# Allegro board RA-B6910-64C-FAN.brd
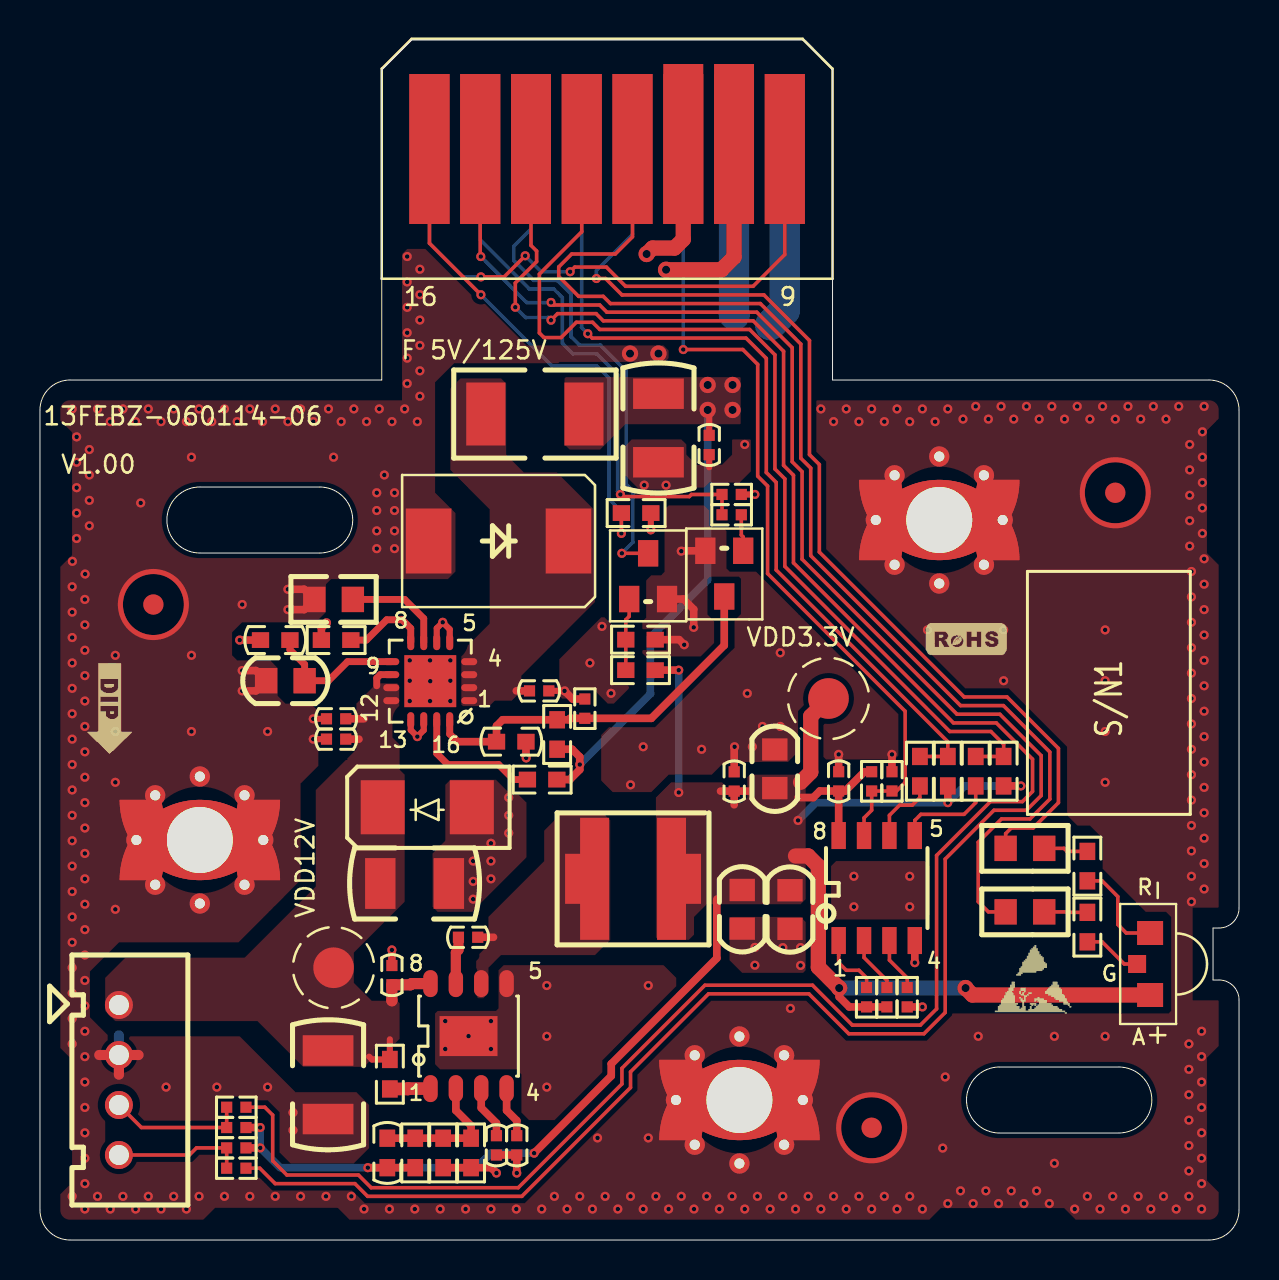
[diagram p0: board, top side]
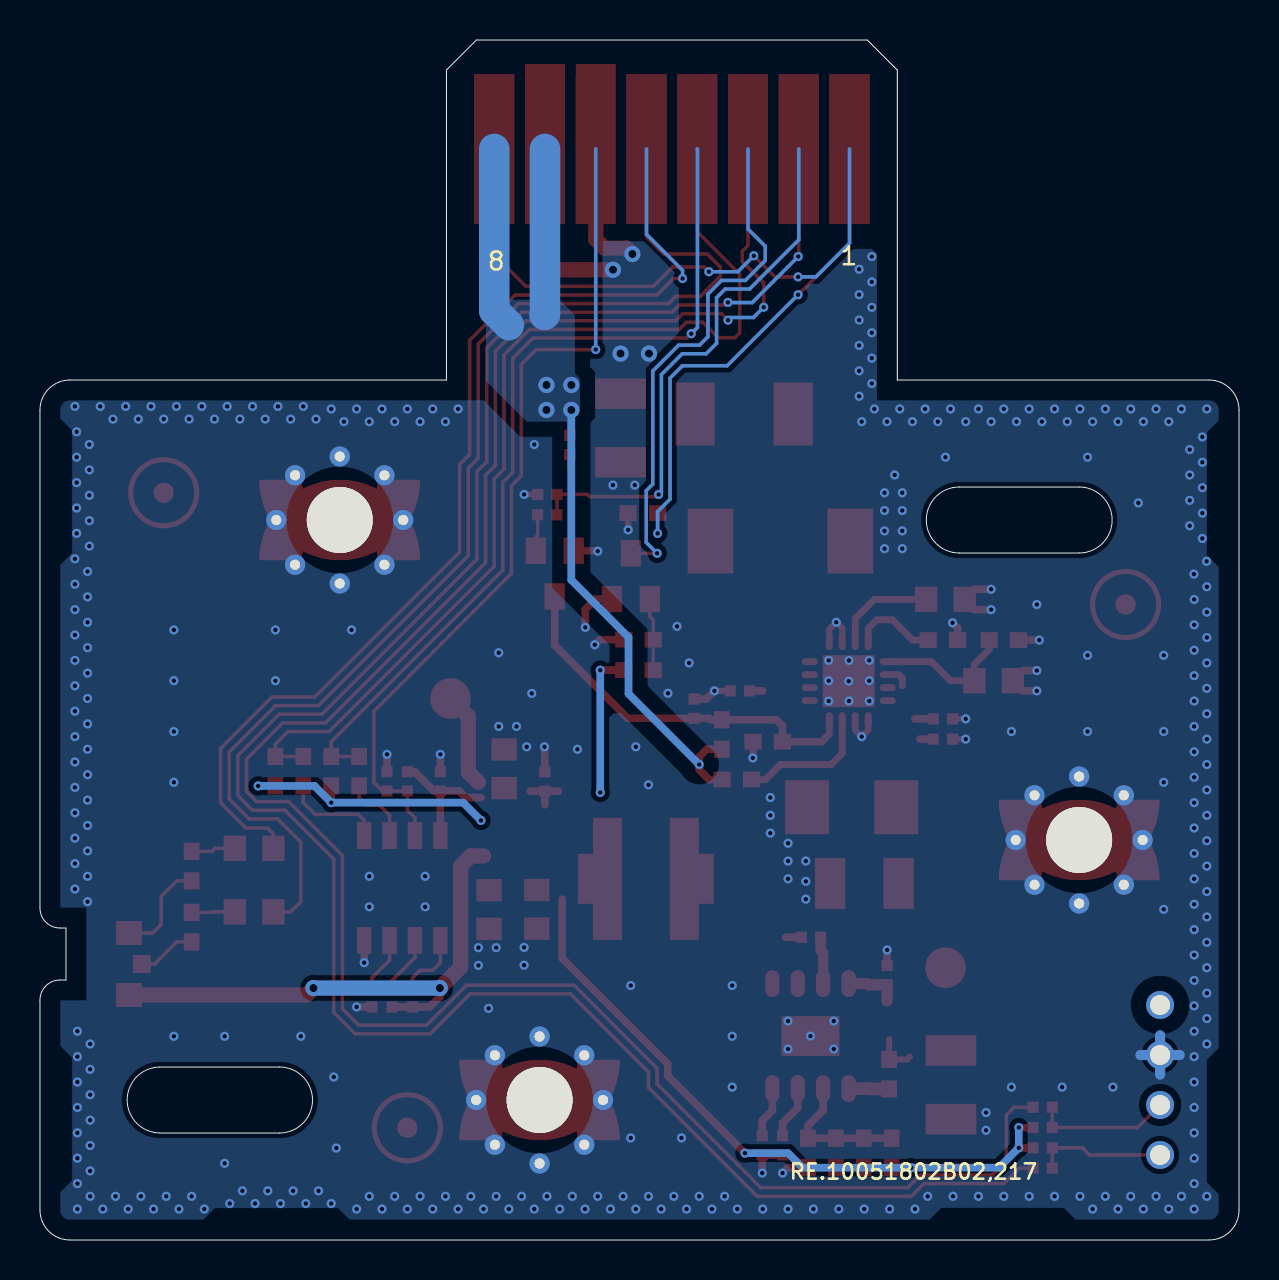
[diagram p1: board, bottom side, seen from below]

Outline 60 x 60 mm; copper layers: TOP, BOTTOM. Coordinates in mm from the lower left corner of the outline.
Outline path: 0,41.5 0,1.5 arc(0.44,0.44) 1.5,0 58.5,0 arc(59.56,0.44) 60,1.5 60,12 arc(59.71,12.71) 59,13 58.7,13 58.7,15.6 59,15.6 arc(59.71,15.89) 60,16.6 60,41.5 arc(59.56,42.56) 58.5,43 39.66,43 39.66,58.5 38.16,60 18.6,60 17.1,58.5 17.1,43 1.5,43 arc(0.44,42.56) 0,41.5 ; 8,37.65 14,37.65 arc(15.65,36) 14,34.35 8,34.35 arc(6.35,36) 8,37.65 ; 48,8.65 54,8.65 arc(55.65,7) 54,5.35 48,5.35 arc(46.35,7) 48,8.65

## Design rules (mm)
nets with their own width: min track width 0.381; nets VDD3.3V

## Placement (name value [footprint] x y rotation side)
C1  X  [C0603]  23.58 24.92 180 top
C2  10uF/25V  [C1210]  18.75 17.83 0 top
C3  10uF/25V  [C1210]  14.42 7.76 270 top
C4  0.1uF/25V  [C0402]  17.61 13.24 90 top
C5  0.1uF/25V  [C0402]  24.98 27.46 0 top
C6  0.1uF/25V  [C0402]  21.42 15.14 0 top
C7  X  [C0603]  17.38 4.35 90 top
C8  1uF/25V  [C0402]  14.82 26.06 180 top
C9  330nF  [C0805]  12.28 27.96 180 top
C10  X  [C0603]  11.77 30 180 top
C11  22uF  [C0805]  37.53 16.52 270 top
C12  X  [C0805]  35.14 16.53 270 top
C13  0.1uF/25V  [C0402]  34.74 22.93 90 top
C14  22uF  [C0805]  36.77 23.56 90 top
C15  1uF/25V  [C0402]  22.84 4.73 270 top
C16  103  [C0402]  23.86 4.73 270 top
C17  0.1uF/25V  [C0402]  39.97 22.93 270 top
C18  10uF/25V  [C1210]  30.95 40.6 270 top
C19  0.1uF/25V  [C0402]  33.49 39.75 270 top
C20  1uF/25V  [C0402]  14.82 25.04 0 top
D1  SMCJ12A  [DO_214AB]  22.95 34.95 180 top
D2  -  [MBRS140T3]  19.38 21.64 0 top
D3  -  [LED_SIDE_2]  55.55 13.8 270 top
F1  5A/125V  [FUSE_0453010]  24.77 41.3 180 top
FD2  -  [MARK]  41.62 5.61 180 top
FD3  -  [MARK]  5.68 31.77 180 top
FD4  -  [MARK]  53.81 37.36 90 top
J1  -  [GF_C210R3_11631_Y]  37.27 54.3 180 top
J3  -  [TJC3_4A]  3.95 11.75 270 top
L1  4.5uH/3A  [NR6045T100M]  29.68 18.06 180 top
L2  100/4A  [L0805]  49.29 16.41 0 top
L3  100/4A  [L0805]  49.29 19.58 0 top
NOREF  -  []  -2 55 0 top
NOREF#2  -  []  49.74 11.96 0 top
NOREF#3  -  []  23.35 7.57 90 top
NOREF#4  -  []  110.22 -1.01 90 top
NOREF#5  -  []  186 -57 180 top
NOREF#6  -  []  -0.99 -7.99 180 top
NOREF#7  -  []  61.01 -39.36 180 top
NOREF#8  -  []  135.78 -0.99 270 top
NOREF#9  -  []  11.78 -0.99 270 top
NOREF#10  -  []  184.99 -39.36 0 top
NOREF#11  -  []  43.78 14.97 90 top
NOREF#12  -  []  -0.99 5.99 180 top
NOREF#13  -  []  172.22 -1.01 90 top
NOREF#14  -  []  46.06 30 0 top
NOREF#15  -  []  60.99 37.36 0 top
NOREF#16  -  []  123.01 -7.99 180 top
NOREF#17  -  []  184.99 37.36 0 top
NOREF#18  -  []  -0.99 37.36 180 top
NOREF#19  -  []  73.78 -0.99 270 top
NOREF#20  -  []  39.33 19.6 0 top
NOREF#21  -  []  4.28 27.2 270 top
NOREF#22  -  []  184.99 5.99 0 top
NOREF#23  -  []  44.41 15.6 90 top
NOREF#24  -  []  20.81 7.57 0 top
NOREF#25  -  []  122.99 5.99 0 top
NOREF#26  -  []  60.99 5.99 0 top
NOREF#27  -  []  18.95 12.19 0 top
NOREF#28  -  []  184.99 -7.99 0 top
NOREF#29  -  []  123.01 -39.36 180 top
NOREF#30  -  []  18.95 8.19 90 top
NOREF#31  -  []  -0.99 -39.36 180 top
NOREF#32  -  []  61.01 -7.99 180 top
NOREF#33  -  []  122.99 37.36 0 top
NOREF#34  -  []  48.22 -1.01 90 top
NOREF#35  -  []  -2 -57 0 bottom
NOREF#36  -  []  186 55 180 bottom
Q1  MMBT3904LT1G  [SOT_23]  30.43 33.19 270 top
Q2  MMBT3904LT1G  [SOT_23]  34.24 33.32 90 top
R1  10K_1%  [R0603]  25.13 23.02 180 top
R2  4.53K_1%  [R0603]  30.05 28.49 180 top
R3  1.91K_1%  [R0603]  30.05 30.02 0 top
R4  10K_1%  [R0603]  17.51 8.29 270 top
R5  10K_1%  [R0603]  18.78 4.35 90 top
R6  47.5K_1%  [R0603]  14.82 30 0 top
R7  200  [R0603]  52.41 15.65 90 top
R8  1K_1%  [R0603]  52.41 18.69 90 top
R9  39K_1%  [R0805]  14.69 32.03 180 top
R10  X  [R0603]  20.18 4.35 270 top
R11  3.01K_1%  [R0603]  21.57 4.35 270 top
R13  4.7K  [R0402]  9.82 4.61 180 top
R16  0  [R0603]  29.83 36.35 0 top
R17  33  [R0402]  9.82 3.59 180 top
R18  4.7K  [R0402]  41.36 12.14 90 top
R19  4.7K  [R0402]  42.38 12.14 90 top
R20  X  [R0402]  42.63 22.93 270 top
R22  0  [R0603]  44.03 23.44 90 top
R24  33  [R0402]  9.82 6.64 0 top
R25  0  [R0603]  46.82 23.44 90 top
R30  4.7K  [R0402]  43.39 12.14 90 top
R31  10K_1%  [R0603]  48.22 23.44 90 top
R33  4.7K  [R0402]  41.62 22.93 270 top
R34  10K_1%  [R0603]  45.43 23.44 90 top
R36  10K_1%  [R0603]  25.88 25.28 90 top
R37  1K  [R0402]  34.61 36.26 0 top
R38  4.7K  [R0402]  27.27 26.57 90 top
R39  4.7K  [R0402]  34.61 37.28 0 top
R40  4.7K  [R0402]  9.82 5.62 180 top
U1  TPS2590RSAR  [QFN_16_EP2M60]  19.53 27.94 180 top
U2  TPS54227  [SOP_8_EP2M90X2M00]  21.45 10.19 0 top
U3  AT24C02C_SSHM_T  [SOP_8]  41.87 17.6 0 top
X1  -  [TEST_80]  39.46 27.08 90 top
X2  -  [SCREW_N_M_3_3MM]  8 20 0 top
X3  -  [SCREW_N_M_3_3MM]  45 36 0 top
X4  -  [SCREW_N_M_3_3MM]  35 7 0 top
X5  -  [TEST_80]  14.69 13.61 270 top

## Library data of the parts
C1-C3 C7 C9-C12 C14 C18 = CAP_NP
C4-C6 C8 C13 C15-C17 C19 C20 = C0402_P: alternate symbols: (c0402;c0402_p)
D1 D2 = DIODE
D3 = LED_SIDE_2
F1 = FUSE
FD2-FD4 = MARK
J1 = GF_C210D7_11631_Y
J3 = TJC3_4A
L1-L3 = Inductor
Q1 Q2 = BCE_NPN
R1-R11 R16 R22 R25 R31 R34 R36 = RESISTOR
R13 R17-R20 R24 R30 R33 R37-R40 = R0402_P: alternate symbols: (r0402;r0402_p)
U1 = TPS2590RSAR
U2 = TPS54227
U3 = 24C02
X1 X5 = TEST_80
X2-X4 = SCREW_N

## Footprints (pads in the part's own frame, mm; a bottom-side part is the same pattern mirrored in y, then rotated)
C0402
  rect 0.559x0.559 smd: 1(-0.483,0) 2(0.483,0)
C0603
  rect 0.864x0.787 smd: 1(-0.737,0) 2(0.737,0)
C0805
  rect 1.118x1.27 smd: 1(-0.965,0) 2(0.965,0)
C1210
  rect 1.524x2.54 smd: 1(-1.714,0) 2(1.714,0)
DO_214AB
  rect 2.286x3.251 smd: 1(3.5,0) 2(-3.5,0)
FUSE_0453010
  rect 1.96x3.15 smd: 1(-2.455,0) 2(2.455,0)
GF_C210R3_11631_Y
  rect 2x7.5 smd: 1(17.78,-0.25) 2(15.24,-0.25) 3(12.7,-0.25) 4(10.16,-0.25) 5(7.62,-0.25) 6(5.08,-0.25) 7(2.54,-0.25) 8(0,-0.25) 9(0,-0.25) 12(7.62,-0.25) 13(10.16,-0.25) 14(12.7,-0.25) 15(15.24,-0.25) 16(17.78,-0.25)
  rect 2x8 smd: 10(2.54,-0.5) 11(5.08,-0.5)
L0805
  rect 1.118x1.27 smd: 1(-0.965,0) 2(0.965,0)
LED_SIDE_2
  rect 1.2x1.3 smd: 1(-1.55,0) 3(1.55,0)
  rect 0.9x0.9 smd: 2(0,-0.65)
MARK
  round 1.016 smd: 1(0,0)
MBRS140T3
  rect 2.2x2.7 smd: 1(2.23,0) 2(-2.23,0)
NR6045T100M
  custom 0.55x0.55 smd: 1(-2.3,0) 2(2.3,0)
QFN_16_EP2M60
  oval 0.8x0.35 smd: 1(-1.95,0.975) 2(-1.95,0.325) 3(-1.95,-0.325) 4(-1.95,-0.975) 9(1.95,-0.975) 10(1.95,-0.325) 11(1.95,0.325) 12(1.95,0.975)
  oval 0.35x0.8 smd: 5(-0.975,-1.95) 6(-0.325,-1.95) 7(0.325,-1.95) 8(0.975,-1.95) 13(0.975,1.95) 14(0.325,1.95) 15(-0.325,1.95) 16(-0.975,1.95)
  rect 2.6x2.6 smd: 17(0,0)
R0402
  rect 0.559x0.559 smd: 1(-0.483,0) 2(0.483,0)
R0603
  rect 0.864x0.787 smd: 1(-0.737,0) 2(0.737,0)
R0805
  rect 1.118x1.27 smd: 1(-0.965,0) 2(0.965,0)
SCREW_N_M_3_3MM
  round 3.3 hole 3.3 unplated: (0,0)
  round 1.016 hole 0.508: 2(-3.175,0) 3(0,3.175) 4(3.175,0) 5(0,-3.175) 6(2.235,2.235) 7(2.235,-2.235) 8(-2.235,-2.235) 9(-2.235,2.235)
  custom 1.003x1.003 smd: 10(0,0) 11(0,0) 12(0,0) 13(0,0)
SOP_8
  rect 0.72x1.35 smd: 1(-1.905,-2.625) 2(-0.635,-2.625) 3(0.635,-2.625) 4(1.905,-2.625) 5(1.905,2.625) 6(0.635,2.625) 7(-0.635,2.625) 8(-1.905,2.625)
SOP_8_EP2M90X2M00
  oval 0.72x1.35 smd: 1(-1.905,-2.625) 2(-0.635,-2.625) 3(0.635,-2.625) 4(1.905,-2.625) 5(1.905,2.625) 6(0.635,2.625) 7(-0.635,2.625) 8(-1.905,2.625)
  rect 2.9x2 smd: 9(0,0)
SOT_23
  rect 1.321x1.016 smd: 1(1.143,-0.947) 2(1.143,0.947) 3(-1.143,0)
TEST_80
  round 2.032 smd: 1(0,0)
TJC3_4A
  round 1.4 hole 1: 1(0,0) 2(2.5,0) 3(5,0) 4(7.5,0)

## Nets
GND: C1.1 C2.2 C3.2 C4.2 C5.2 C8.2 C9.2 C10.2 C11.2 C12.2 C13.2 C14.2 C15.2 C16.2 C17.1 C18.2 C19.2 C20.1 D1.1 D2.1 J1.10(GND_2) J1.11(GND_1) J3.2 Q1.2(E) Q2.2(E) R3.2 R6.1 R9.2 R10.2 R11.2 R16.2 R20.1 R30.1 R38.2 R39.2 U1.5(GND_1) U1.6(R\T\R\Y\) U1.13(GND_2) U1.14(GND_3) U1.17(EPAD) U2.5(GND) U2.9(EPAD) U3.4(GND) X2.2 X2.3 X2.4 X2.5 X2.6 X2.7 X2.8 X2.9 X2.10 X2.11 X2.12 X2.13 X3.2 X3.3 X3.4 X3.5 X3.6 X3.7 X3.8 X3.9 X3.10 X3.11 X3.12 X3.13 X4.2 X4.3 X4.4 X4.5 X4.6 X4.7 X4.8 X4.9 X4.10 X4.11 X4.12 X4.13
VDD3.3V: C7.1 C11.1 C12.1 C13.1 C14.1 C17.2 D3.3(A) L1.1 R2.1 R5.1 R13.1 R18.1 R19.1 R31.1 R33.1 R34.1 R40.1 U3.8(VCC) X1.1
VDD12V: C2.1 C3.1 C4.1 C8.1 C20.2 D2.2 J3.1 R4.1 U1.10(OUT_1) U1.11(OUT_2) U1.12(OUT_3) U2.8(VIN) X5.1
VDD12V_IN: C18.1 C19.1 F1.1 J1.7 J1.8 R1.1 R36.1
FAN_E2_WP: J1.6 R20.2 R33.2 U3.7(WP)
FAN_EN: J1.2 R37.1 R39.1
FAN_LED_GREEN: J1.5 L3.1
FAN_LED_RED: J1.12 L2.1
FAN_POWER_OK#: J1.3 Q1.3(C)
FAN_PWM: J1.15 R17.1
FAN_SCL: J1.4 R22.2 R34.2
FAN_SDA: J1.13 R25.2 R31.2
FAN_TACH: J1.14 R24.2
PRESENT1: J1.1 J1.9
PWM: J3.4 R13.2 R17.2
TACH: J3.3 R24.1 R40.2
TPS2590_EN#: C1.2 Q2.3(C) R36.2 R38.1 U1.16(E\N\)
N356833: C5.1 D1.2 F1.2 U1.1(IN_1) U1.2(IN_2) U1.3(IN_3) U1.4(IN_4)
N16771214: R1.2 U1.15(F\L\T\)
N16771504: R9.1 U1.7(ILIM)
N16771512: R6.2 U1.8(IFLT)
N16772013: C9.1 C10.1 U1.9(CT)
N16778426: C7.2 R5.2 R10.1 R11.1 U2.2(VFB)
N16778448: R4.2 U2.1(EN)
N16778454: C6.1 U2.7(VBST)
N16778460: C15.1 U2.3(VREG5)
N16778464: C16.1 U2.4(SS)
N16778490: C6.2 L1.2 U2.6(SW)
N16779888: Q1.1(B) R2.2 R3.1
N16780436: R18.2 U3.1(A0)
N16780442: R19.2 U3.2(A1)
N16780525: R22.1 U3.6(SCL)
N16780537: R25.1 U3.5(SDA)
N16780545: R30.2 U3.3(A2)
N16791501: Q2.1(B) R37.2
N16806499: J1.16 R16.1
N16830240: D3.2(G) R7.1
N16830247: D3.1(R) R8.1
N16830309: L2.2 R7.2
N16830337: L3.2 R8.2

Pads without a net: FD2 1; FD3 1; FD4 1

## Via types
v1: diameter 0.457, hole 0.229, TOP to BOTTOM, 389 vias
v2: diameter 0.813, hole 0.406, TOP to BOTTOM, 10 vias

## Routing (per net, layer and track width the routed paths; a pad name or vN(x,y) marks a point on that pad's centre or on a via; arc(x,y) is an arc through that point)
GND: length 56.9
  TOP w0.305: R16.2 v1(30.57,35.51) ; C20.1 v1(13.68,25.04) ; U1.13 18.55,25.5 v1(18.88,25.17) 19.2,25.49 U1.14 ; R39.2 v1(35.77,37.28) ; U1.5 20.5,30.53 v1(20.15,30.89) 19.85,30.59 U1.6 ; C5.2 v1(26.25,27.46) ; C19.2 33.49,38.63 ; C8.2 v1(13.68,26.06)
  TOP w0.381: v1(10.12,28.47) 10.81,28.47 C9.2 10.81,27.46 v1(10.12,27.46) ; v1(32.09,34.44) 32.11,34.46 Q2.2 ; C1.1 24.32,24.16 24.33,24.15 v1(24.33,24.1) ; v1(22.84,3.35) 22.57,3.62 R11.2 R10.2 ; Q1.2 32.2,32.05 32.71,31.53 v1(32.71,30.63) ; U3.4 v1(43.78,13.87) ; R38.2 26.66,27.05 v1(26.25,27.46) ; v1(23.86,3.35) C16.2 C15.2 ; R20.1 v1(42.63,24.28) ; R6.1 14.08,30.61 v1(14.34,30.86) ; R30.1 v1(44.16,11.65) ; v1(34.76,24.66) 34.74,24.64 C13.2 ; v1(32.24,29.76) 31.98,30.02 R3.2 ; C10.2 v1(9.99,30) ; v1(12.41,32.54) 13.22,32.54 R9.2 13.22,31.52 v1(12.41,31.52) ; C4.2 v1(17.61,14.5) ; C17.1 v1(39.97,24.28)
  TOP w0.508: 2.97,9.25 J3.2 ; J3.2 4.93,9.25 ; J3.2 3.95,8.27
  TOP w0.762: J1.11 32.19,50.03 31.75,49.6 30.65,49.6 v2(30.36,49.3) ; J1.10 34.73,49.14 34.1,48.51 v2(31.33,48.51)
  BOTTOM w0.508: J3.2 3.95,10.23 ; J3.2 3.95,8.27 ; J3.2 4.93,9.25 ; J3.2 2.97,9.25
  vias: v1(1.61,41.55) v1(1.62,33.93) v1(1.61,32.66) v1(1.61,31.39) v1(1.61,30.12) v1(1.61,28.85) v1(1.61,27.58) v1(1.61,26.31) v1(1.61,25.04) v1(1.61,23.77) v1(1.61,22.5) v1(1.61,21.23) v1(1.61,19.96) v1(1.61,18.69) v1(1.61,17.42) v1(1.61,16.15) v1(1.61,14.88) v1(1.61,13.61) v1(1.61,12.34) v1(1.61,11.07) v1(1.61,9.8) v1(1.61,2.18) v1(1.83,40.16) v1(1.83,38.89) v1(1.83,37.62) v1(1.83,36.35) v1(1.83,35.08) v1(2.26,33.3) v1(2.25,32.03) v1(2.25,30.76) v1(2.25,29.49) v1(2.25,28.22) v1(2.25,26.95) v1(2.25,25.68) v1(2.25,24.41) v1(2.25,23.14) v1(2.25,21.87) v1(2.25,20.6) v1(2.25,19.33) v1(2.25,18.06) v1(2.25,16.79) v1(2.25,15.52) v1(2.25,14.25) v1(2.25,12.98) v1(2.25,11.71) v1(2.25,10.44) v1(2.25,9.17) v1(2.25,7.9) v1(2.25,6.63) v1(2.25,5.36) v1(2.25,4.09) v1(2.25,2.82) v1(2.25,1.55) v1(2.47,39.52) v1(2.47,38.25) v1(2.47,36.98) v1(2.47,35.71) v1(2.88,41.55) v1(2.88,2.18) v1(3.52,40.92) v1(3.52,1.55) v1(3.77,29.23) v1(3.77,25.42) v1(3.77,22.88) v1(3.77,16.53) v1(4.15,41.55) v1(4.15,2.18) v1(4.79,40.92) v1(4.79,1.55) v1(5.04,36.85) v1(5.42,41.55) v1(5.42,2.18) v1(6.06,40.92) v1(6.06,1.55) v1(6.31,7.64) v1(6.69,41.55) v1(6.69,2.18) v1(7.33,40.92) v1(7.33,1.55) v1(7.58,39.14) v1(7.58,29.23) v1(7.58,25.42) v1(7.96,41.55) v1(7.96,2.18) v1(8.6,40.92) v1(8.85,7.64) v1(9.23,41.55) v1(9.23,2.18) v1(9.87,40.92) v1(10.12,31.77) v1(10.5,41.55) v1(10.5,2.18) v1(11.14,40.92) v1(11.39,25.42) v1(11.39,7.64) v1(11.77,41.55) v1(11.77,2.18) v1(12.41,40.92) v1(12.66,6.37) v1(12.66,5.49) v1(13.04,41.55) v1(13.04,2.18) v1(13.68,40.92) v1(14.31,2.18) v1(14.44,41.55) v1(14.69,39.14) v1(15.07,40.92) v1(15.58,2.18) v1(15.71,41.55) v1(16.22,1.55) v1(16.34,40.92) v1(16.85,37.36) v1(16.85,36.47) v1(16.85,35.46) v1(16.85,34.57) v1(16.98,41.55) v1(17.23,38.25) v1(17.49,1.55) v1(17.61,40.92) v1(17.74,37.36) v1(17.74,36.47) v1(17.74,35.46) v1(17.74,34.57) v1(18.25,41.55) v1(18.38,49.17) v1(18.38,47.9) v1(18.38,46.63) v1(18.38,45.36) v1(18.38,44.09) v1(18.38,42.82) v1(18.5,28.98) v1(18.5,27.96) v1(18.5,26.95) v1(18.76,1.55) v1(18.88,40.92) v1(19.01,48.54) v1(19.01,47.27) v1(19.01,46) v1(19.01,44.73) v1(19.01,43.46) v1(19.01,42.19) v1(19.52,28.98) v1(19.53,27.94) v1(19.52,26.95) v1(20.03,1.55) v1(20.28,10.95) v1(20.28,9.55) v1(20.53,28.98) v1(20.53,27.96) v1(20.53,26.95) v1(21.3,1.55) v1(21.45,10.19) v1(21.68,18.95) v1(21.68,17.93) v1(21.68,17.04) v1(22.57,19.84) v1(22.57,18.95) v1(22.57,18.06) v1(22.57,10.95) v1(22.57,9.55) v1(22.57,1.55) v1(23.46,22.12) v1(23.46,21.23) v1(23.46,20.34) v1(23.84,1.55) v1(25.11,1.55) v1(25.36,12.72) v1(25.36,10.18) v1(25.36,7.64) v1(25.74,2.18) v1(26.38,1.55) v1(27.01,2.18) v1(27.52,28.85) v1(27.65,1.55) v1(27.9,5.1) v1(28.12,30.68) v1(28.28,2.18) v1(28.57,27.33) v1(28.92,1.55) v1(29.55,22.76) v1(29.55,2.18) v1(30.19,24.66) v1(30.19,1.55) v1(30.24,37.74) v1(30.44,12.72) v1(30.44,5.1) v1(30.82,2.18) v1(31.33,37.74) v1(31.46,1.55) v1(32.09,2.18) v1(32.73,1.55) v1(33.11,24.54) v1(33.36,2.18) v1(34,1.55) v1(34.63,2.18) v1(35.27,39.78) v1(35.27,1.55) v1(35.39,27.33) v1(35.65,24.66) v1(35.77,14.63) v1(35.77,13.74) v1(35.9,2.18) v1(36.16,25.68) v1(36.54,1.55) v1(37.04,29.36) v1(37.04,25.68) v1(37.17,14.62) v1(37.17,2.18) v1(37.55,11.58) v1(37.81,1.55) v1(38.06,14.62) v1(38.06,13.73) v1(38.44,2.18) v1(39.08,41.55) v1(39.08,1.55) v1(39.71,40.92) v1(39.71,2.18) v1(40.35,41.55) v1(40.35,1.55) v1(40.73,18.19) v1(40.73,16.66) v1(40.98,40.92) v1(40.98,2.18) v1(41.62,41.55) v1(41.62,1.55) v1(42.25,40.92) v1(42.25,2.18) v1(42.89,41.55) v1(42.89,1.55) v1(43.52,40.92) v1(43.52,18.19) v1(43.52,16.66) v1(43.52,2.18) v1(44.16,41.55) v1(44.16,1.55) v1(44.41,30.5) v1(44.79,40.92) v1(45.17,4.6) v1(45.3,8.15) v1(45.43,41.55) v1(45.43,1.82) v1(46.06,2.46) v1(46.19,41.05) v1(46.7,1.82) v1(46.82,41.68) v1(46.95,10.18) v1(47.33,2.46) v1(47.46,41.05) v1(47.97,1.82) v1(48.09,41.68) v1(48.22,30.5) v1(48.22,27.96) v1(48.6,2.46) v1(48.73,41.05) v1(49.24,1.82) v1(49.36,41.68) v1(49.87,2.46) v1(50,41.05) v1(50.51,1.82) v1(50.63,41.68) v1(50.76,10.18) v1(50.76,3.83) v1(51.27,41.05) v1(51.78,1.55) v1(51.9,41.68) v1(52.41,2.18) v1(52.54,41.05) v1(53.05,1.55) v1(53.17,41.68) v1(53.3,30.5) v1(53.3,27.96) v1(53.3,25.42) v1(53.3,22.88) v1(53.3,10.18) v1(53.68,2.18) v1(53.81,41.05) v1(54.32,1.55) v1(54.44,41.68) v1(54.95,2.18) v1(55.08,41.05) v1(55.59,1.55) v1(55.71,41.68) v1(56.22,2.18) v1(56.35,41.05) v1(56.86,1.55) v1(56.98,41.68) v1(57.49,9.8) v1(57.49,8.53) v1(57.49,7.26) v1(57.49,5.99) v1(57.49,4.72) v1(57.49,3.45) v1(57.49,2.18) v1(57.53,39.78) v1(57.53,38.51) v1(57.53,37.24) v1(57.53,35.97) v1(57.53,34.7) v1(57.62,33.43) v1(57.62,32.16) v1(57.62,30.89) v1(57.62,29.62) v1(57.62,28.35) v1(57.62,27.08) v1(57.62,25.81) v1(57.62,24.54) v1(57.62,23.27) v1(57.62,22) v1(57.62,20.73) v1(57.62,19.46) v1(57.62,18.19) v1(57.62,16.92) v1(58.17,40.41) v1(58.17,39.14) v1(58.17,37.87) v1(58.17,36.6) v1(58.17,35.33) v1(58.13,10.44) v1(58.13,9.17) v1(58.13,7.9) v1(58.13,6.63) v1(58.13,5.36) v1(58.13,4.09) v1(58.13,2.82) v1(58.13,1.55) v1(58.25,41.68) v1(58.25,34.06) v1(58.25,32.79) v1(58.25,31.52) v1(58.25,30.25) v1(58.25,28.98) v1(58.25,27.71) v1(58.25,26.44) v1(58.25,25.17) v1(58.25,23.9) v1(58.25,22.63) v1(58.25,21.36) v1(58.25,20.09) v1(58.25,18.82) v1(58.25,17.55) v2(29.53,44.32) v2(30.95,44.32)
VDD3.3V: length 96.5
  TOP w0.381: 37.93,22.12 38.7,22.12 39.02,22.45 C17.2 ; v2(39.99,12.6) 39.99,12.16 40.5,11.65 R18.1 R19.1 ; 33.87,17.04 33.87,14.09 28.59,8.81 28.59,8.2 v1(24.73,4.34) ; R40.1 v1(11.02,5.62) ; R5.1 C7.1 v1(16.4,3.62) ; R33.1 41.26,23.41 40.29,22.45 C17.2 ; C17.2 U3.8 ; 34.74,21.76 C13.1 ; C13.1 35.46,22.44 ; C13.1 34.06,22.44 ; R2.1 v1(31.96,28.49) ; R13.1 v1(11.02,4.61) ; R34.1 v1(45.43,21.87) ; R31.1 v1(49.08,22.7)
  TOP w0.762: v2(39.99,12.6) 38.95,13.64 38.95,18.69 38.44,19.2 37.81,19.2 ; 38.06,22.88 38.57,23.39 38.57,26.19 X1.1 ; v2(46.32,12.6) 46.66,12.25 D3.3
  BOTTOM w0.381: v1(11.02,5.62) 11.02,4.61 v1(11.02,4.61) 12.01,3.62 v1(16.4,3.62) 21.84,3.62 22.57,4.34 v1(24.73,4.34) ; v1(31.96,28.49) v1(31.96,22.38) ; v1(49.08,22.7) 46.26,22.7 v1(45.43,21.87) 38.82,21.87 v1(37.93,20.98)
  BOTTOM w0.762: v2(46.32,12.6) v2(39.99,12.6)
VDD12V: length 7.6
  TOP w0.305: 17.51,10.04 R4.1 16.61,9.03 16.47,9.17
  TOP w0.343: U1.10 17.03,28.27 16.85,28.09 16.85,27.71
  TOP w0.381: C20.2 15.96,25.04 ; C8.1 16.22,26.06
  TOP w0.559: 17.61,11.96 17.61,11.97 C4.1 18.54,12.76 18.6,12.82 U2.8
VDD12V_IN: length 42.4
  TOP w0.305: C19.1 33.49,41.43 v2(33.41,41.5)
  TOP w0.381: R1.1 26.51,23.02 27.01,23.52 v1(27.01,23.77) 27.01,24.15 26.63,24.54 R36.1
  BOTTOM w0.381: v1(27.01,23.77) 30.55,27.31 30.55,30.14 33.41,33 v2(33.41,41.5)
  BOTTOM w1.524: J1.7 34.73,46.28 34.76,46.25 ; J1.8 37.27,46.48 36.54,45.74
  vias: v2(33.41,42.75) v2(34.66,42.75) v2(34.66,41.5)
FAN_E2_WP: length 42.3
  TOP w0.178: v1(32.19,44.52) 35.17,44.52 35.91,43.78 35.91,38.19 36.41,37.7 36.41,33.32 43.29,26.44 43.29,22.88 42.86,22.45 R20.2 R33.2 41.62,21.49 41.24,21.11 U3.7
  BOTTOM w0.178: v1(32.19,44.52) J1.6
FAN_EN: length 27.8
  TOP w0.178: R37.1 R39.1 32.6,37.28 32.49,37.17 29.15,37.17 v1(29.04,37.28)
  BOTTOM w0.178: v1(29.04,37.28) 28.9,37.42 28.9,43.27 27.86,44.31 26.67,44.31 26.14,44.83 26.14,47.12 25.71,47.55 24.49,47.55 22.03,50.01 J1.2
FAN_LED_GREEN: length 52.7
  TOP w0.178: v1(27.84,48.07) 28.3,48.07 29.12,47.25 36.23,47.25 38.5,44.98 38.5,39.27 39,38.77 39,34.4 46.25,27.15 48.39,27.15 50.96,24.58 50.96,21.87 49.7,20.6 48.6,20.6 48.32,20.32 L3.1
  BOTTOM w0.178: v1(27.84,48.07) 27.84,48.48 29.65,50.29 J1.5
FAN_LED_RED: length 60.9
  TOP w0.178: J1.12 29.65,50.16 28.79,49.3 26.61,49.3 25.96,48.65 25.96,48.18 26.95,47.18 28.19,47.18 28.55,46.82 36.05,46.82 38.07,44.8 38.07,39.09 38.57,38.59 38.57,34.22 46.07,26.72 48.21,26.72 50.53,24.4 50.53,22.04 49.54,21.06 48.12,21.06 46.95,19.89 46.95,16.92 47.46,16.41 L2.1
FAN_POWER_OK#: length 25.9
  TOP w0.178: v1(29.12,34.33) Q1.3
  BOTTOM w0.178: J1.3 24.57,50.55 23.71,49.69 23.71,48.98 24.7,47.98 25.89,47.98 26.57,47.3 26.57,45.16 27,44.74 28.04,44.74 29.34,43.45 29.34,37.79 29.67,37.46 29.67,34.88 v1(29.12,34.33)
FAN_PWM: length 107
  TOP w0.178: v1(25.57,46.88) 25.7,46.75 28.01,46.75 28.37,46.39 35.87,46.39 37.64,44.62 37.64,38.91 38.14,38.42 38.14,34.04 45.89,26.29 48.03,26.29 50.1,24.22 50.1,22.22 49.36,21.49 47.74,21.49 45.3,19.05 45.3,11.38 44.23,10.31 40.47,10.31 38.48,12.31 33.45,12.31 29.55,8.41 29.55,7.62 24.11,2.18 16.39,2.18 15.76,2.82 11.77,2.82 11,3.59 R17.1 ; v1(22.06,49.17) 22.03,49.2 J1.15
  BOTTOM w0.178: v1(25.57,46.88) 25.56,46.87 24.36,46.87 v1(22.06,49.17)
FAN_SCL: length 43.9
  TOP w0.178: v1(27.41,45.31) 27.63,45.09 35.33,45.09 36.35,44.08 36.35,38.37 36.84,37.88 36.84,33.5 45.43,24.92 R34.2 R22.2
  BOTTOM w0.178: J1.4 27.1,54.54 27.1,45.63 v1(27.41,45.31)
FAN_SDA: length 50.4
  TOP w0.178: R25.2 R31.2 48.22,24.79 47.59,25.42 45.53,25.42 37.27,33.68 37.27,38.06 36.78,38.55 36.78,44.26 35.51,45.53 28.01,45.53 27.65,45.89 26.84,45.89 26.07,45.12 25.22,45.12 24.99,45.35 24.99,48.3 27.11,50.41 J1.13
FAN_TACH: length 108.7
  TOP w0.178: v1(25.57,45.99) 25.9,46.32 27.83,46.32 28.19,45.96 35.69,45.96 37.21,44.44 37.21,38.73 37.7,38.24 37.7,33.86 45.71,25.86 47.85,25.86 49.67,24.04 49.67,22.43 49.16,21.92 47.56,21.92 44.87,19.23 44.87,11.56 44.05,10.74 40.65,10.74 38.66,12.74 33.27,12.74 29.12,8.59 29.12,7.8 23.93,2.61 16.57,2.61 15.94,3.25 12.36,3.25 11.64,3.96 11.64,6.25 11.25,6.64 R24.2 ; J1.14 24.57,49.73 24.85,49.45 24.85,48.92 23.79,47.85 v1(23.79,46.64)
  BOTTOM w0.178: v1(25.57,45.99) 25.44,46.13 24.3,46.13 v1(23.79,46.64)
PRESENT1: length 30.4
  TOP w0.178: J1.9 37.27,49.27 35.68,47.69 29.3,47.69 28.34,48.65 26.76,48.65 v1(26.53,48.41) ; v1(24.28,49.21) 23.23,48.16 v1(22.06,48.16)
  BOTTOM w0.178: v1(24.28,49.21) 25.08,48.41 26.53,48.41 v1(26.53,48.41) ; J1.1 19.49,49.84 21.17,48.16 v1(22.06,48.16)
PWM: length 6.6
  TOP w0.178: R17.2 R13.2 7.83,4.61 7.48,4.25 J3.4
TACH: length 6.9
  TOP w0.178: R24.1 R40.2 5.08,5.62 J3.3
TPS2590_EN#: length 19.5
  TOP w0.343: U1.16 20.5,25.3 20.71,25.09
  TOP w0.381: 20.71,25.09 20.88,24.92 C1.2 22.85,25.7 23.15,26.01 R36.2 26.46,26.01 26.53,26.08 R38.1 30.59,26.08 34.24,29.73 Q2.3
N356833: length 0.7
  TOP w0.381: C5.1 23.84,27.46
N16771214: length 6.7
  TOP w0.343: U1.15 19.85,24.33 20.41,23.77 22.95,23.77 23.7,23.02 R1.2
N16771504: length 5.1
  TOP w0.343: R9.1 18.25,32.03 19.2,31.07 U1.7
N16771512: length 4.3
  TOP w0.343: U1.8 18.55,30.58 18.12,31.01 17.35,31.01 16.33,30 R6.2
N16772013: length 7.1
  TOP w0.343: C10.1 12.51,29.51 13.24,28.78 C9.1 14.44,27.96 15.39,28.92 U1.9
N16778426: length 7
  TOP w0.381: U2.2 20.81,6.48 21.57,5.72 R11.1 R10.1 R5.2 C7.2
N16778448: length 2
  TOP w0.635: U2.1 18.43,7.57 18.41,7.55 R4.2
N16778454: length 2.4
  TOP w0.508: U2.7 20.81,14.37 20.94,14.5 C6.1
N16778460: length 2.7
  TOP w0.381: U2.3 22.08,6.61 22.84,5.84 C15.1
N16778464: length 2.6
  TOP w0.381: U2.4 23.35,6.48 23.86,5.97 C16.1
N16778490: length 0.8
  TOP w0.381: C6.2 22.69,15.14
N16779888: length 3.6
  TOP w0.178: Q1.1 29.48,31.18 29.31,31.01 R3.1 R2.2
N16780436: length 3.3
  TOP w0.178: U3.1 39.97,14.25 39.97,14.25 39.97,13.87 40.35,13.49 40.98,13.49 41.36,13.1 R18.2
N16780442: length 2.8
  TOP w0.178: R19.2 42.38,12.98 41.24,14.12 U3.2
N16780525: length 3.5
  TOP w0.178: R22.1 44.03,22.7 44.03,22.12 43.65,21.74 43.01,21.74 42.51,21.23 U3.6
N16780537: length 5
  TOP w0.178: U3.5 43.78,20.98 44.08,21.28 46.24,21.28 46.82,21.87 R25.1
N16780545: length 2.7
  TOP w0.178: R30.2 43.39,13.1 42.51,13.99 U3.3
N16791501: length 1.8
  TOP w0.178: R37.2 35.09,35.25 35.19,35.15 Q2.1
N16806499: length 25.5
  TOP w0.178: R16.1 v1(29.09,35.33) ; J1.16 19.49,49.84 21.17,48.16 21.17,48.16 v1(22.06,47.26)
  BOTTOM w0.178: v1(29.09,35.33) 29.09,36.42 28.47,37.04 28.47,43.09 27.85,43.71 25.61,43.71 v1(22.06,47.26)
N16830240: length 2.9
  TOP w0.178: D3.2 54.26,13.8 53.15,14.91 R7.1
N16830247: length 5
  TOP w0.178: R8.1 53.15,17.96 53.94,17.17 53.94,15.77 54.36,15.35 D3.1
N16830309: length 2.2
  TOP w0.178: L2.2 51.37,16.41 51.4,16.38 R7.2
N16830337: length 2.2
  TOP w0.178: L3.2 51.24,19.58 51.4,19.43 R8.2

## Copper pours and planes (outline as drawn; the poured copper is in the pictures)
GND on TOP (solid shape): outline of 184 points within 3.9,30 7.45,33.55
GND on TOP (solid shape): outline of 184 points within 39.84,3.83 43.39,7.39
GND on TOP (solid shape): outline of 184 points within 52.03,35.58 55.59,39.14
GND on TOP: 24.47,5.99 24.09,6.37 24.09,8.28 23.84,8.53 20.03,8.53 19.77,8.79 19.77,11.33 19.9,11.45 22.82,11.45 22.95,11.58 22.95,13.49 23.2,13.74 31.2,13.74 31.84,13.11 31.84,11.96 25.87,5.99
GND on TOP: 1.5,1.02 1.16,1.16 1.02,1.5 1.02,41.5 1.16,41.84 1.5,41.98 18.12,41.98 18.12,49.3 18.38,49.55 19.77,49.55 22.06,47.27 22.06,47.01 24.34,44.73 31.2,44.73 31.46,44.47 31.46,44.09 31.2,43.84 29.93,43.84 30.31,43.46 32.22,43.46 32.66,43.9 32.85,43.71 35.39,43.71 35.39,44.09 35.14,44.35 33.11,44.35 32.47,44.98 30.31,44.98 30.19,44.86 30.19,45.87 29.81,46.25 34,46.25 34.76,47.01 36.03,45.74 36.16,45.87 36.16,46.38 37.93,44.6 37.93,41.43 38.06,41.3 38.74,41.98 58.5,41.98 58.84,41.84 58.98,41.5 58.98,16.62 57.68,16.62 57.68,11.98 58.98,11.98 58.98,1.5 58.84,1.16 58.5,1.02 ; 21 cut-outs
GND on TOP: 20.53,23.01 22.82,23.01 23.58,22.25 23.96,22.25 24.34,21.87 24.34,19.07 21.68,16.41 19.9,16.41 19.65,16.66 19.65,19.33 20.28,19.96 20.28,22.76
GND on TOP: 34.63,16.15 38.06,16.15 38.31,15.9 38.31,13.49 38.19,13.36 35.14,13.36 34.5,13.99 34.5,16.03
GND on BOTTOM: 1.5,1.02 1.16,1.16 1.02,1.5 1.02,41.5 1.16,41.84 1.5,41.98 18.12,41.98 18.12,49.3 18.12,49.3 18.38,49.55 19.78,49.55 24.85,44.49 27.28,44.49 27.9,43.86 28.89,43.86 29.21,44.18 28.03,45.36 28.03,48.31 29.65,49.94 32.07,49.94 32.07,46.38 32.38,46.07 33.44,47.12 33.44,49.94 38.64,49.94 38.64,45.95 38.09,45.39 38.09,42.92 37.43,42.26 37.43,42.14 37.58,41.98 58.5,41.98 58.84,41.84 58.98,41.5 58.98,16.62 57.68,16.62 57.68,11.98 58.98,11.98 58.98,1.5 58.84,1.16 58.5,1.02 ; 1 cut-out
VDD3.3V on TOP: 30.95,15.01 30.82,15.14 30.82,22.12 31.58,22.88 34.12,22.88 34.25,22.76 34.25,22 34.38,21.87 35.14,21.87 35.39,22.12 35.39,23.14 35.52,23.27 38.19,23.27 38.31,23.14 38.31,17.04 38.06,16.79 33.36,16.79 32.73,16.15 32.73,15.26 32.47,15.01
VDD12V on TOP: 3.26,13.11 3.26,11.45 3.77,10.95 10.88,10.95 13.17,8.66 16.22,8.66 16.72,9.17 16.72,9.55 16.98,9.8 17.74,9.8 17.99,10.06 17.99,11.84 17.87,11.96 16.6,11.96 15.71,12.85 15.71,14.38 18.25,16.92 18.25,23.27 17.99,23.52 17.99,27.71 17.87,27.84 16.85,27.84 15.84,26.82 15.84,24.54 13.8,22.5 13.8,17.68 10.25,14.12 4.28,14.12
VDD12V_IN on TOP: 28.03,39.52 29.3,40.79 35.27,40.79 35.65,41.17 35.65,42.95 35.46,43.14 26.31,43.14 26.25,43.08 26.25,39.78 26.5,39.52
VDD12V_IN on BOTTOM: 36.92,47.01 34,47.01 33.23,46.25 33.23,43.33 32.98,43.08 32.98,41.43 33.49,40.92 35.65,40.92 37.68,42.95 37.68,46.25
N356833 on TOP: 21.17,26.69 21.04,26.82 21.04,29.36 22.5,30.82 22.5,36.54 20.53,38.51 20.53,42.57 21.04,43.08 23.07,43.08 23.33,42.82 23.33,39.27 24.22,38.38 25.87,38.38 27.77,36.47 27.77,31.9 24.09,28.22 24.09,27.46 23.33,26.69
N16778490 on TOP: 21.93,12.09 21.68,12.34 21.68,13.99 22.44,14.76 22.44,16.15 25.23,18.95 25.23,20.47 26,21.23 28.28,21.23 28.54,20.98 28.54,15.01 27.77,14.25 23.07,14.25 22.44,13.61 22.44,12.34 22.19,12.09

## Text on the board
Ref Des/Silkscreen Bottom: RE.10051802B02,217
Ref Des/Silkscreen Top: 13FEBZ-060114-06 | V1.00 | F 5V/125V | VDD3.3V | VDD12V | S/N1
User.11: FIGURE | SIZE | 9.0 | 16.0 | 20.0 | 39.37 | 129.92 | DRILL CHART: TOP to BOTTOM | ALL UNITS ARE IN MILS | PLATED | NON-PLATED | QTY | 389 | 10 | 24 | 4 | 3
